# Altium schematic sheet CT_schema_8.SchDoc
size 278 x 170 mm
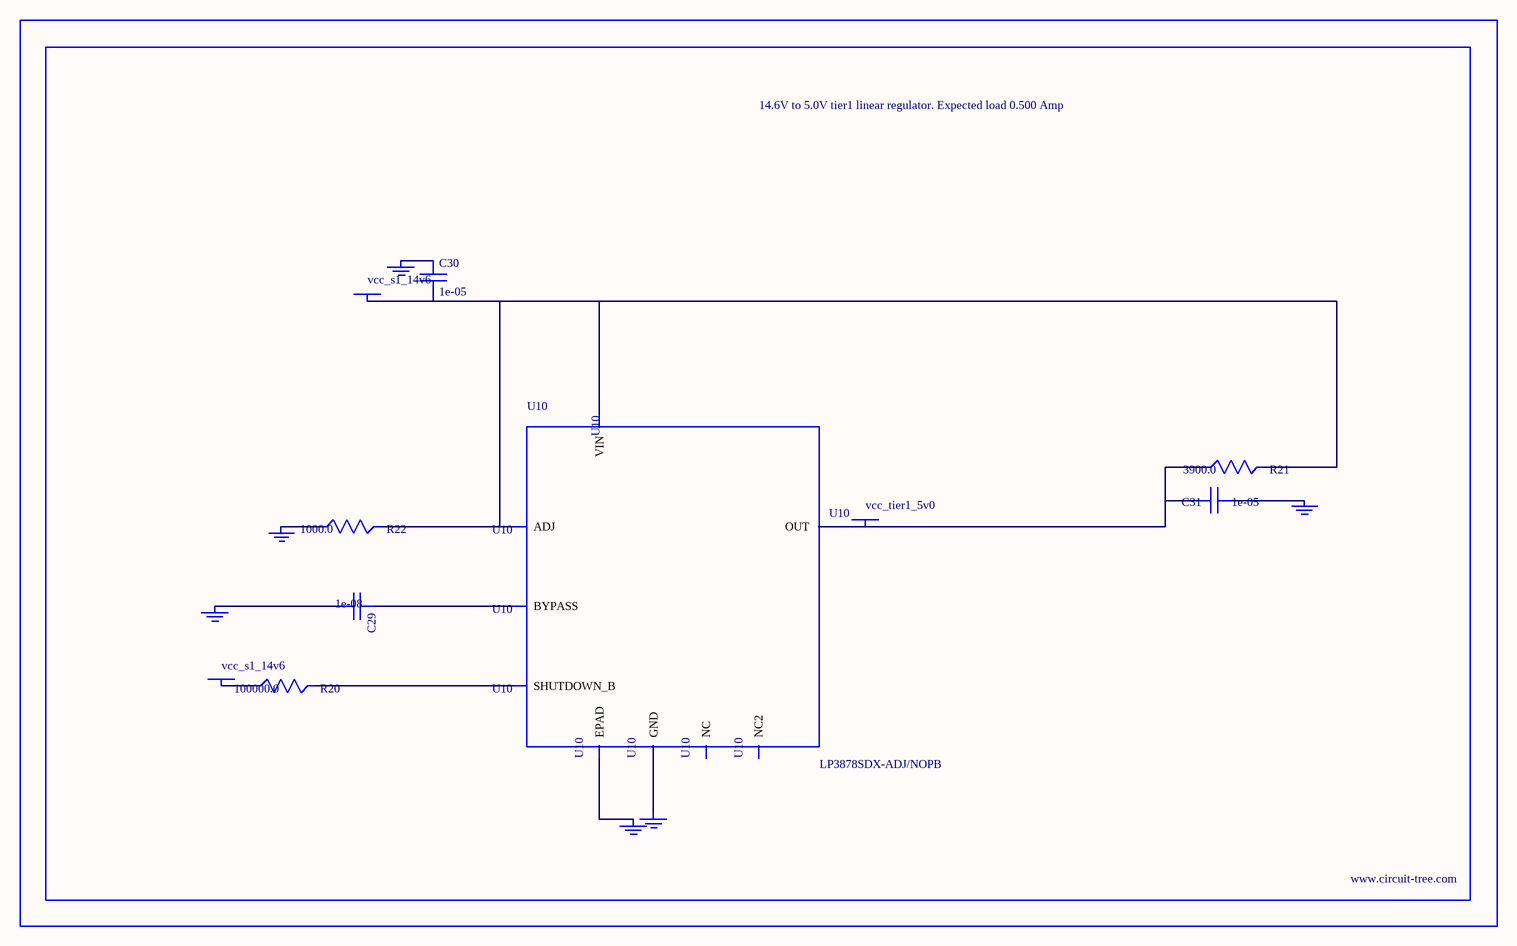
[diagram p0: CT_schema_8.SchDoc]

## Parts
BORDER7  (no value)
C29  1e-08  [C0402]
C30  1e-05  [C1210]
C31  1e-05  [C1210]
GND_INSTANCE_7_0  (no value)
GND_INSTANCE_7_1  (no value)
GND_INSTANCE_7_2  (no value)
GND_INSTANCE_7_3  (no value)
GND_INSTANCE_7_4  (no value)
GND_INSTANCE_7_5  (no value)
POWER_INSTANCE_7_0  vcc_s1_14v6
POWER_INSTANCE_7_1  vcc_s1_14v6
POWER_INSTANCE_7_2  vcc_tier1_5v0
R20  100000.0  [R0603]
R21  3900.0  [R0603]
R22  1000.0  [R0603]
U10  LP3878SDX-ADJ/NOPB  [WSON-8]

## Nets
NetC29_1: C29.1 U10.1(BYPASS)
NetC29_2: C29.2 GND_INSTANCE_7_0.0(GND)
NetC30_1: C30.1 GND_INSTANCE_7_1.0(GND)
NetC30_2: C30.2 POWER_INSTANCE_7_0.0(PWR) R21.2 R22.2 U10.4(VIN) U10.6(ADJ)
NetC31_1: C31.1 GND_INSTANCE_7_2.0(GND)
NetC31_2: C31.2 POWER_INSTANCE_7_2.0(PWR) R21.1 U10.5(OUT)
NetGND_INSTANCE_7_3_0: GND_INSTANCE_7_3.0(GND) R22.1
NetGND_INSTANCE_7_4_0: GND_INSTANCE_7_4.0(GND) U10.PAD(EPAD)
NetGND_INSTANCE_7_5_0: GND_INSTANCE_7_5.0(GND) U10.3(GND)
NetPOWER_INSTANCE_7_1_0: POWER_INSTANCE_7_1.0(PWR) R20.1
NetR20_2: R20.2 U10.8(SHUTDOWN_B)

Not connected (* = marked no-connect by the designer): U10 2(NC) 7(NC2)

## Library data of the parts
BORDER7 = BORDER_PAGE7
C29 = C0402C103K3RAC
C30 = C1210C106K5PACTU
C31 = GRM32DR61E106MA12L
GND_INSTANCE_7_0-GND_INSTANCE_7_5 = GND
POWER_INSTANCE_7_0-POWER_INSTANCE_7_2 = PWR
R20 = RC0603JR-07100KL
R21 = RC0603JR-073K9L
R22 = RC0603JR-071KL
